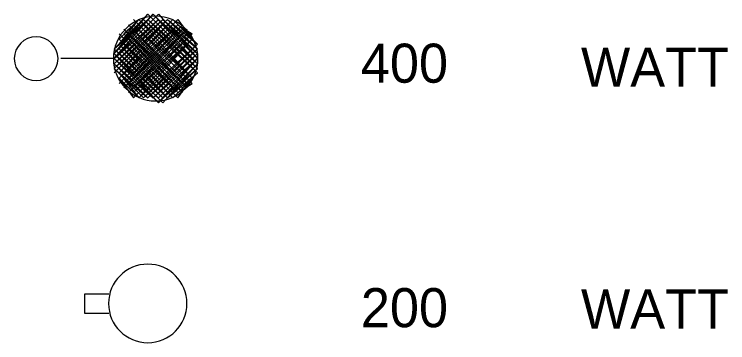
# Model space of a CAD drawing. Extents: x 10019.5 to 10026.1, y 9984.8 to 9994.8.
# Drawn here: x 10019.527 to 10020.622, y 9991.76 to 9992.264 of the extents above; entities that cross this region are included whole.
import ezdxf

# ---------------------------------------------------------------- set-up
doc = ezdxf.new("R2010")
doc.units = 0
doc.layers.add('DETL-LINE', color=7, linetype='Continuous')
doc.layers.add('DETL-NOTE', color=7, linetype='Continuous')

msp = doc.modelspace()

# ---------------------------------------------------------------- linework, layer by layer
at = {"layer": 'DETL-LINE'}
for p, q in [((10019.68, 9992.2107), (10019.732, 9992.2637)), ((10019.68, 9992.2037), (10019.732, 9992.2637)), ((10019.68, 9992.2037), (10019.74, 9992.2637)), ((10019.68, 9992.2037), (10019.74, 9992.2637)), ((10019.68, 9992.2037), (10019.74, 9992.2637)), ((10019.68, 9992.1957), (10019.74, 9992.2637)), ((10019.68, 9992.1957), (10019.74, 9992.2637)), ((10019.68, 9992.1957), (10019.748, 9992.2637)), ((10019.68, 9992.1957), (10019.748, 9992.2637)), ((10019.68, 9992.2107), (10019.732, 9992.2557)), ((10019.68, 9992.2107), (10019.732, 9992.2557)), ((10019.68, 9992.2107), (10019.732, 9992.2557)), ((10019.68, 9992.1957), (10019.748, 9992.2557)), ((10019.68, 9992.1877), (10019.748, 9992.2557)), ((10019.68, 9992.1877), (10019.748, 9992.2557)), ((10019.68, 9992.1877), (10019.748, 9992.2557)), ((10019.68, 9992.1877), (10019.755, 9992.2557)), ((10019.68, 9992.1877), (10019.755, 9992.2557)), ((10019.68, 9992.1877), (10019.755, 9992.2557)), ((10019.68, 9992.1877), (10019.755, 9992.2557)), ((10019.68, 9992.1807), (10019.755, 9992.2557)), ((10019.68, 9992.1807), (10019.762, 9992.2557)), ((10019.68, 9992.1807), (10019.762, 9992.2557)), ((10019.68, 9992.1807), (10019.762, 9992.2557)), ((10019.68, 9992.1807), (10019.762, 9992.2557)), ((10019.68, 9992.1807), (10019.762, 9992.2557)), ((10019.68, 9992.1737), (10019.762, 9992.2557)), ((10019.688, 9992.2257), (10019.718, 9992.2557)), ((10019.688, 9992.2257), (10019.718, 9992.2557)), ((10019.688, 9992.2177), (10019.718, 9992.2557)), ((10019.688, 9992.2177), (10019.718, 9992.2557)), ((10019.688, 9992.2177), (10019.725, 9992.2557)), ((10019.688, 9992.2177), (10019.725, 9992.2557)), ((10019.688, 9992.2107), (10019.725, 9992.2557)), ((10019.688, 9992.1737), (10019.762, 9992.2557)), ((10019.688, 9992.1737), (10019.762, 9992.2557)), ((10019.688, 9992.1737), (10019.77, 9992.2557)), ((10019.688, 9992.1737), (10019.77, 9992.2557)), ((10019.688, 9992.1737), (10019.77, 9992.2557)), ((10019.688, 9992.1737), (10019.77, 9992.2557)), ((10019.688, 9992.1737), (10019.77, 9992.2557)), ((10019.688, 9992.1657), (10019.77, 9992.2557)), ((10019.688, 9992.1657), (10019.77, 9992.2557)), ((10019.688, 9992.1657), (10019.77, 9992.2557)), ((10019.688, 9992.1657), (10019.778, 9992.2557)), ((10019.688, 9992.1657), (10019.778, 9992.2557)), ((10019.688, 9992.1657), (10019.778, 9992.2557)), ((10019.71, 9992.2557), (10019.8, 9992.1657)), ((10019.718, 9992.2557), (10019.808, 9992.1737)), ((10019.718, 9992.2557), (10019.808, 9992.1737)), ((10019.718, 9992.2557), (10019.8, 9992.1657)), ((10019.718, 9992.2557), (10019.8, 9992.1657)), ((10019.718, 9992.2557), (10019.8, 9992.1657)), ((10019.718, 9992.2557), (10019.8, 9992.1657)), ((10019.718, 9992.2557), (10019.8, 9992.1657)), ((10019.725, 9992.2557), (10019.808, 9992.1807)), ((10019.725, 9992.2557), (10019.808, 9992.1807)), ((10019.725, 9992.2557), (10019.808, 9992.1807)), ((10019.725, 9992.2557), (10019.808, 9992.1737)), ((10019.725, 9992.2557), (10019.808, 9992.1737)), ((10019.725, 9992.2557), (10019.808, 9992.1737)), ((10019.725, 9992.2557), (10019.808, 9992.1737)), ((10019.725, 9992.2557), (10019.808, 9992.1737)), ((10019.732, 9992.2637), (10019.808, 9992.1877)), ((10019.732, 9992.2637), (10019.808, 9992.1877)), ((10019.732, 9992.2557), (10019.808, 9992.1877)), ((10019.732, 9992.2557), (10019.808, 9992.1807)), ((10019.732, 9992.2557), (10019.808, 9992.1807)), ((10019.732, 9992.2557), (10019.808, 9992.1807)), ((10019.732, 9992.2557), (10019.808, 9992.1807)), ((10019.74, 9992.2637), (10019.808, 9992.1957)), ((10019.74, 9992.2637), (10019.808, 9992.1877)), ((10019.74, 9992.2637), (10019.808, 9992.1877)), ((10019.74, 9992.2637), (10019.808, 9992.1877)), ((10019.74, 9992.2637), (10019.808, 9992.1877)), ((10019.748, 9992.2637), (10019.808, 9992.1957)), ((10019.748, 9992.2637), (10019.808, 9992.1957)), ((10019.748, 9992.2557), (10019.808, 9992.2037)), ((10019.748, 9992.2557), (10019.808, 9992.2037)), ((10019.748, 9992.2557), (10019.808, 9992.1957)), ((10019.748, 9992.2557), (10019.808, 9992.1957)), ((10019.755, 9992.2557), (10019.808, 9992.2107)), ((10019.755, 9992.2557), (10019.808, 9992.2107)), ((10019.755, 9992.2557), (10019.808, 9992.2037)), ((10019.755, 9992.2557), (10019.808, 9992.2037)), ((10019.755, 9992.2557), (10019.808, 9992.2037)), ((10019.762, 9992.2557), (10019.808, 9992.2177)), ((10019.762, 9992.2557), (10019.808, 9992.2107)), ((10019.762, 9992.2557), (10019.808, 9992.2107)), ((10019.77, 9992.2557), (10019.8, 9992.2257)), ((10019.77, 9992.2557), (10019.808, 9992.2177)), ((10019.77, 9992.2557), (10019.808, 9992.2177)), ((10019.77, 9992.2557), (10019.808, 9992.2177)), ((10019.778, 9992.2557), (10019.8, 9992.2257)), ((10019.688, 9992.1657), (10019.778, 9992.2477)), ((10019.688, 9992.1657), (10019.778, 9992.2477)), ((10019.688, 9992.1657), (10019.778, 9992.2477)), ((10019.688, 9992.1577), (10019.778, 9992.2477)), ((10019.695, 9992.2337), (10019.71, 9992.2477)), ((10019.695, 9992.1577), (10019.778, 9992.2477)), ((10019.695, 9992.1577), (10019.778, 9992.2477)), ((10019.695, 9992.1577), (10019.785, 9992.2477)), ((10019.695, 9992.1577), (10019.785, 9992.2477)), ((10019.695, 9992.1577), (10019.785, 9992.2477)), ((10019.695, 9992.1577), (10019.785, 9992.2477)), ((10019.695, 9992.1577), (10019.785, 9992.2477)), ((10019.695, 9992.1507), (10019.785, 9992.2477)), ((10019.695, 9992.1507), (10019.785, 9992.2477)), ((10019.702, 9992.2477), (10019.792, 9992.1577)), ((10019.702, 9992.2477), (10019.792, 9992.1577)), ((10019.702, 9992.2477), (10019.792, 9992.1507)), ((10019.702, 9992.2477), (10019.792, 9992.1507)), ((10019.71, 9992.2477), (10019.8, 9992.1657)), ((10019.71, 9992.2477), (10019.8, 9992.1657)), ((10019.71, 9992.2477), (10019.8, 9992.1657)), ((10019.71, 9992.2477), (10019.8, 9992.1577)), ((10019.71, 9992.2477), (10019.8, 9992.1577)), ((10019.71, 9992.2477), (10019.8, 9992.1577)), ((10019.71, 9992.2477), (10019.8, 9992.1577)), ((10019.71, 9992.2477), (10019.8, 9992.1577)), ((10019.71, 9992.2477), (10019.8, 9992.1577)), ((10019.778, 9992.2477), (10019.8, 9992.2337)), ((10019.688, 9992.2337), (10019.778, 9992.1437)), ((10019.695, 9992.2337), (10019.702, 9992.2407)), ((10019.695, 9992.1507), (10019.785, 9992.2407)), ((10019.695, 9992.1507), (10019.785, 9992.2407)), ((10019.695, 9992.1507), (10019.785, 9992.2407)), ((10019.695, 9992.1507), (10019.792, 9992.2407)), ((10019.695, 9992.2407), (10019.792, 9992.1507)), ((10019.695, 9992.2407), (10019.785, 9992.1507)), ((10019.695, 9992.2407), (10019.785, 9992.1507)), ((10019.695, 9992.2407), (10019.785, 9992.1507)), ((10019.695, 9992.2407), (10019.785, 9992.1437)), ((10019.695, 9992.2407), (10019.785, 9992.1437)), ((10019.695, 9992.2337), (10019.785, 9992.1437)), ((10019.695, 9992.2337), (10019.785, 9992.1437)), ((10019.695, 9992.2337), (10019.785, 9992.1437)), ((10019.695, 9992.2337), (10019.785, 9992.1437)), ((10019.695, 9992.2337), (10019.785, 9992.1437)), ((10019.695, 9992.2337), (10019.778, 9992.1437)), ((10019.695, 9992.2337), (10019.778, 9992.1437)), ((10019.702, 9992.1507), (10019.792, 9992.2407)), ((10019.702, 9992.1507), (10019.792, 9992.2407)), ((10019.702, 9992.1507), (10019.792, 9992.2407)), ((10019.702, 9992.1507), (10019.792, 9992.2407)), ((10019.702, 9992.1507), (10019.792, 9992.2407)), ((10019.702, 9992.1507), (10019.792, 9992.2407)), ((10019.702, 9992.1437), (10019.792, 9992.2407)), ((10019.702, 9992.1437), (10019.792, 9992.2407)), ((10019.702, 9992.2407), (10019.792, 9992.1507)), ((10019.702, 9992.2407), (10019.792, 9992.1507)), ((10019.702, 9992.2407), (10019.792, 9992.1507)), ((10019.702, 9992.2407), (10019.792, 9992.1507)), ((10019.702, 9992.2407), (10019.792, 9992.1507)), ((10019.702, 9992.2407), (10019.792, 9992.1507)), ((10019.702, 9992.1437), (10019.792, 9992.2337)), ((10019.702, 9992.1437), (10019.8, 9992.2337)), ((10019.71, 9992.1437), (10019.8, 9992.2337)), ((10019.71, 9992.1437), (10019.8, 9992.2337)), ((10019.71, 9992.1437), (10019.8, 9992.2337)), ((10019.71, 9992.1437), (10019.8, 9992.2337)), ((10019.71, 9992.1437), (10019.8, 9992.2337)), ((10019.71, 9992.1437), (10019.8, 9992.2337)), ((10019.785, 9992.2407), (10019.8, 9992.2337)), ((10019.688, 9992.2257), (10019.778, 9992.1437)), ((10019.688, 9992.2257), (10019.778, 9992.1437)), ((10019.688, 9992.2257), (10019.778, 9992.1437)), ((10019.688, 9992.2257), (10019.778, 9992.1357)), ((10019.688, 9992.2257), (10019.778, 9992.1357)), ((10019.688, 9992.2257), (10019.778, 9992.1357)), ((10019.688, 9992.2257), (10019.77, 9992.1357)), ((10019.688, 9992.2257), (10019.77, 9992.1357)), ((10019.688, 9992.2257), (10019.77, 9992.1357)), ((10019.71, 9992.1437), (10019.8, 9992.2257)), ((10019.71, 9992.1437), (10019.8, 9992.2257)), ((10019.71, 9992.1437), (10019.8, 9992.2257)), ((10019.71, 9992.1357), (10019.8, 9992.2257)), ((10019.718, 9992.1357), (10019.8, 9992.2257)), ((10019.718, 9992.1357), (10019.8, 9992.2257)), ((10019.718, 9992.1357), (10019.8, 9992.2257)), ((10019.718, 9992.1357), (10019.8, 9992.2257)), ((10019.718, 9992.1357), (10019.8, 9992.2257)), ((10019.68, 9992.2107), (10019.762, 9992.1357)), ((10019.68, 9992.2107), (10019.762, 9992.1357)), ((10019.68, 9992.2107), (10019.762, 9992.1357)), ((10019.68, 9992.2107), (10019.762, 9992.1357)), ((10019.68, 9992.2107), (10019.755, 9992.1357)), ((10019.68, 9992.2107), (10019.755, 9992.1357)), ((10019.688, 9992.2177), (10019.77, 9992.1357)), ((10019.688, 9992.2177), (10019.77, 9992.1357)), ((10019.688, 9992.2177), (10019.77, 9992.1357)), ((10019.688, 9992.2177), (10019.77, 9992.1357)), ((10019.688, 9992.2177), (10019.77, 9992.1357)), ((10019.688, 9992.2177), (10019.762, 9992.1357)), ((10019.688, 9992.2177), (10019.762, 9992.1357)), ((10019.688, 9992.2107), (10019.762, 9992.1357)), ((10019.718, 9992.1357), (10019.808, 9992.2177)), ((10019.718, 9992.1357), (10019.808, 9992.2177)), ((10019.725, 9992.1357), (10019.808, 9992.2177)), ((10019.725, 9992.1357), (10019.808, 9992.2177)), ((10019.725, 9992.1357), (10019.808, 9992.2177)), ((10019.725, 9992.1357), (10019.808, 9992.2177)), ((10019.725, 9992.1357), (10019.808, 9992.2177)), ((10019.725, 9992.1357), (10019.808, 9992.2177)), ((10019.725, 9992.1357), (10019.808, 9992.2107)), ((10019.725, 9992.1357), (10019.808, 9992.2107)), ((10019.732, 9992.1357), (10019.808, 9992.2107)), ((10019.732, 9992.1357), (10019.808, 9992.2107)), ((10019.732, 9992.1357), (10019.808, 9992.2107)), ((10019.732, 9992.1357), (10019.808, 9992.2107)), ((10019.68, 9992.2037), (10019.755, 9992.1357)), ((10019.68, 9992.2037), (10019.755, 9992.1277)), ((10019.68, 9992.2037), (10019.755, 9992.1277)), ((10019.68, 9992.2037), (10019.755, 9992.1277)), ((10019.68, 9992.2037), (10019.748, 9992.1277)), ((10019.68, 9992.2037), (10019.748, 9992.1277)), ((10019.68, 9992.2037), (10019.748, 9992.1277)), ((10019.732, 9992.1357), (10019.808, 9992.2037)), ((10019.732, 9992.1357), (10019.808, 9992.2037)), ((10019.732, 9992.1357), (10019.808, 9992.2037)), ((10019.74, 9992.1357), (10019.808, 9992.2037)), ((10019.74, 9992.1357), (10019.808, 9992.2037)), ((10019.74, 9992.1357), (10019.808, 9992.2037)), ((10019.74, 9992.1357), (10019.808, 9992.2037)), ((10019.68, 9992.1957), (10019.598, 9992.1957)), ((10019.68, 9992.1957), (10019.748, 9992.1277)), ((10019.68, 9992.1957), (10019.748, 9992.1277)), ((10019.68, 9992.1957), (10019.748, 9992.1357)), ((10019.68, 9992.1957), (10019.74, 9992.1357)), ((10019.68, 9992.1957), (10019.74, 9992.1357)), ((10019.68, 9992.1877), (10019.74, 9992.1357)), ((10019.68, 9992.1877), (10019.74, 9992.1357)), ((10019.68, 9992.1877), (10019.74, 9992.1357)), ((10019.68, 9992.1877), (10019.732, 9992.1357)), ((10019.74, 9992.1357), (10019.808, 9992.1957)), ((10019.748, 9992.1357), (10019.808, 9992.1957)), ((10019.748, 9992.1277), (10019.808, 9992.1957)), ((10019.748, 9992.1277), (10019.808, 9992.1957)), ((10019.748, 9992.1277), (10019.808, 9992.1957)), ((10019.748, 9992.1277), (10019.808, 9992.1877)), ((10019.748, 9992.1277), (10019.808, 9992.1877)), ((10019.755, 9992.1277), (10019.808, 9992.1877)), ((10019.755, 9992.1277), (10019.808, 9992.1877)), ((10019.755, 9992.1277), (10019.808, 9992.1877)), ((10019.68, 9992.1807), (10019.732, 9992.1357)), ((10019.68, 9992.1807), (10019.732, 9992.1357)), ((10019.68, 9992.1807), (10019.732, 9992.1357)), ((10019.68, 9992.1807), (10019.732, 9992.1357)), ((10019.68, 9992.1807), (10019.725, 9992.1357)), ((10019.755, 9992.1357), (10019.808, 9992.1807)), ((10019.762, 9992.1357), (10019.808, 9992.1807)), ((10019.762, 9992.1357), (10019.808, 9992.1807)), ((10019.762, 9992.1357), (10019.808, 9992.1807)), ((10019.688, 9992.1737), (10019.725, 9992.1357)), ((10019.688, 9992.1737), (10019.725, 9992.1357)), ((10019.688, 9992.1737), (10019.718, 9992.1357)), ((10019.688, 9992.1657), (10019.718, 9992.1357)), ((10019.688, 9992.1657), (10019.718, 9992.1357)), ((10019.688, 9992.1657), (10019.71, 9992.1357)), ((10019.762, 9992.1357), (10019.808, 9992.1737)), ((10019.77, 9992.1357), (10019.808, 9992.1737)), ((10019.77, 9992.1357), (10019.808, 9992.1737)), ((10019.77, 9992.1357), (10019.808, 9992.1737)), ((10019.77, 9992.1357), (10019.8, 9992.1657)), ((10019.778, 9992.1357), (10019.8, 9992.1657)), ((10019.695, 9992.1577), (10019.71, 9992.1437)), ((10019.695, 9992.1577), (10019.702, 9992.1507)), ((10019.778, 9992.1437), (10019.8, 9992.1577)), ((10019.785, 9992.1507), (10019.792, 9992.1577))]:
    msp.add_line(p, q, dxfattribs=at)
msp.add_lwpolyline([(10019.672, 9991.8047), (10019.635, 9991.8047), (10019.635, 9991.8347), (10019.672, 9991.8347)], dxfattribs=at)
for centre, radius, start, end in [((10019.7438, 9992.1957), 0.0649, 0, 180), ((10019.7438, 9992.1957), 0.0649, 0, 180), ((10019.5603, 9992.1957), 0.0336, 0, 180), ((10019.5603, 9992.1957), 0.0336, 180, 0), ((10019.7438, 9992.1957), 0.0649, 180, 0), ((10019.7438, 9992.1957), 0.0649, 180, 0), ((10019.7317, 9991.8202), 0.0602, 0, 180), ((10019.7317, 9991.8202), 0.0602, 180, 0)]:
    msp.add_arc(centre, radius, start, end, dxfattribs=at)

# ---------------------------------------------------------------- texts
at = {"layer": 'DETL-NOTE'}
for s, p in [('400', (10020.059, 9992.1587)), ('WATT', (10020.397, 9992.1527)), ('200', (10020.059, 9991.7837)), ('WATT', (10020.397, 9991.7817))]:
    msp.add_text(s, height=0.06, dxfattribs=at).set_placement(p)

doc.saveas('drawing.dxf')
